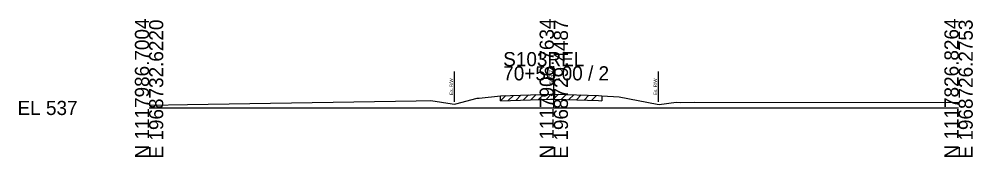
# Model space of a CAD drawing. Extents: x -26 to 163, y -10 to 24518.
# Drawn here: x -25.7 to 162.8, y 18990.3 to 19017.6 of the extents above; entities that cross this region are included whole.
import ezdxf

# ---------------------------------------------------------------- set-up
doc = ezdxf.new("R2010")
doc.units = 0
for name, color, linetype in [('RD_GPK_XS_Cell', 7, 'Continuous'), ('RD_XS_ExGround', 7, 'Continuous'), ('RD_XS_ExPaveRet', 7, 'Continuous'), ('RD_XS_ExRW', 7, 'Continuous'), ('RD_XS_TX_Elev_EX', 7, 'Continuous')]:
    doc.layers.add(name, color=color, linetype=linetype)

msp = doc.modelspace()

# ---------------------------------------------------------------- linework, layer by layer
at = {"layer": 'RD_GPK_XS_Cell'}
for p, q in [((80, 19000), (80, 19008.25)), ((0, 19000), (80, 19000)), ((80, 19000), (160, 19000))]:
    msp.add_line(p, q, dxfattribs=at)
at = {"layer": 'RD_XS_ExGround'}
msp.add_lwpolyline([(0, 19000.58), (7.58, 19000.65), (52.81, 19001.42), (55.72, 19001.46), (59.94, 19000.78), (60.31, 19000.72), (60.64, 19000.81), (64.88, 19001.9), (65.26, 19001.94), (69.47, 19002.4), (79.32, 19002.72), (80.17, 19002.75), (88.83, 19002.45), (89.47, 19002.42), (92.95, 19002.18), (100.46, 19000.73), (100.81, 19000.66), (104.19, 19001.13), (105.12, 19001.09), (107.83, 19001.12), (160, 19001.1)], dxfattribs=at)
at = {"layer": 'RD_XS_ExPaveRet'}
for p, q in [((69.47, 19001.4), (70.5, 19002.43)), ((69.47, 19001.4), (69.47, 19002.4)), ((70.97, 19001.45), (72, 19002.48)), ((72.47, 19001.5), (73.5, 19002.53)), ((73.97, 19001.54), (75, 19002.58)), ((75.47, 19001.59), (76.5, 19002.63)), ((76.97, 19001.64), (78, 19002.68)), ((78.47, 19001.69), (79.5, 19002.73)), ((79.97, 19001.74), (80.95, 19002.72)), ((81.47, 19001.7), (82.44, 19002.67)), ((82.97, 19001.65), (83.94, 19002.62)), ((84.47, 19001.6), (85.44, 19002.57)), ((85.97, 19001.55), (86.94, 19002.51)), ((87.47, 19001.49), (88.44, 19002.46)), ((89.47, 19002.42), (89.47, 19001.42)), ((69.47, 19001.4), (79.32, 19001.72)), ((79.32, 19001.72), (80.17, 19001.75)), ((80.17, 19001.75), (88.83, 19001.45)), ((88.83, 19001.45), (89.47, 19001.42))]:
    msp.add_line(p, q, dxfattribs=at)
at = {"layer": 'RD_XS_ExRW'}
for p, q in [((60.31, 19007.22), (60.31, 19001.22)), ((100.64, 19007.19), (100.64, 19001.19))]:
    msp.add_line(p, q, dxfattribs=at)

# ---------------------------------------------------------------- texts
at = {"layer": 'RD_GPK_XS_Cell'}
for s, p in [('N 1117986.7004', (0, 18990)), ('E 1968732.6220', (2.8, 18990)), ('N 1117906.7634', (80, 18990)), ('E 1968729.4487', (82.8, 18990)), ('N 1117826.8264', (160, 18990)), ('E 1968726.2753', (162.8, 18990))]:
    msp.add_text(s, height=2.8, rotation=90, dxfattribs=at).set_placement(p)
for s, p in [('S103REL', (70, 19008.25)), ('70+50.00 / 2', (70, 19005.45)), ('EL 537', (-26, 18998.6))]:
    msp.add_text(s, height=2.8, dxfattribs=at).set_placement(p)
at = {"layer": 'RD_XS_ExRW'}
for p in [(60.06, 19002.57), (100.39, 19002.54)]:
    msp.add_text('Ex. R/W ', height=0.65, rotation=90, dxfattribs=at).set_placement(p)
at = {"layer": 'RD_XS_TX_Elev_EX'}
msp.add_text('539.74', height=0.8, rotation=90, dxfattribs=at).set_placement((79.9, 19004.74))

doc.saveas('drawing.dxf')
